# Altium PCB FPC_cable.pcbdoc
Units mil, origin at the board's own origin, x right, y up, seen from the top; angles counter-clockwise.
Board outline 8390 x 1932.5 mil, 2 copper layers (Top Layer, Bottom Layer); 1 components, 14 nets, 59 pads, 21 vias.
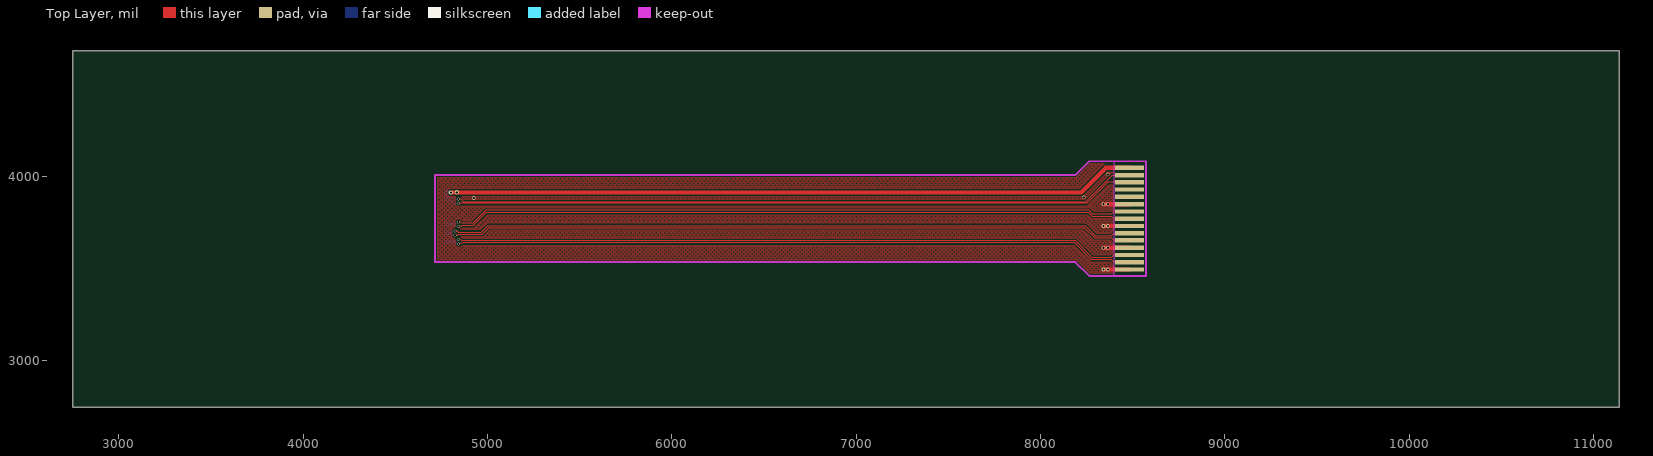
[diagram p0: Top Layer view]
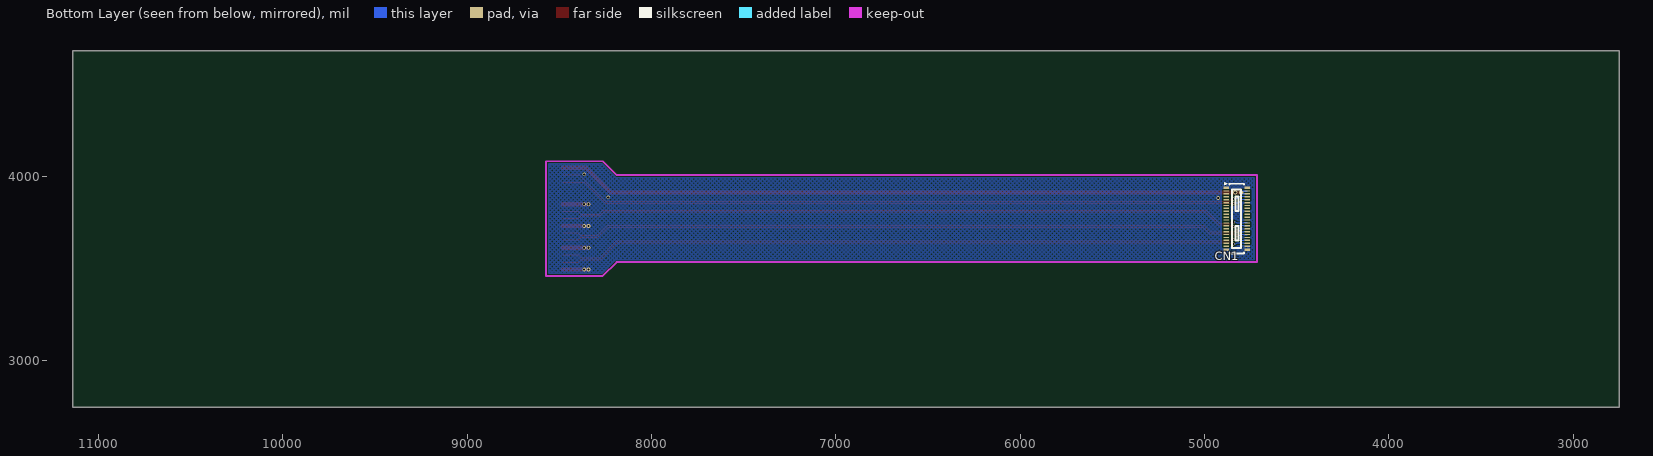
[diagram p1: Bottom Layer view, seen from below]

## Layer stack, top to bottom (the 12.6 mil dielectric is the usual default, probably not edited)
Top Layer: signal copper (thickness not stored)
Dielectric: dielectric 12.6, FR-4, Dk 4.8
Bottom Layer: signal copper (thickness not stored)

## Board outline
11140,2750 2750,2750 2750,4682.5 11140,4682.5

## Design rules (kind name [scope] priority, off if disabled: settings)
BoardOutlineClearance copperThickness1oz [All] p0: genericclearance=10 ignorepadtopadclearanceinfootprint=FALSE except(0: Arc-SplitContinuation Track-SplitContinuation SMDPad-SplitContinuation THPad-SplitContinuation Via-SplitContinuation Fill-SplitContinuation Poly-SplitContinuation Region-SplitContinuation Text-SplitContinuation; 6: SMDPad-CutoutEdge THPad-CutoutEdge Via-CutoutEdge Fill-CutoutEdge Region-CutoutEdge; 11.8: Track-OutlineEdge SMDPad-OutlineEdge THPad-OutlineEdge Via-OutlineEdge Fill-OutlineEdge Region-OutlineEdge Poly-OutlineEdge Text-OutlineEdge Track-CutoutEdge)
BoardOutlineClearance copperThickness2oz [All] p0: genericclearance=10 ignorepadtopadclearanceinfootprint=FALSE except(0: Arc-SplitContinuation Track-SplitContinuation SMDPad-SplitContinuation THPad-SplitContinuation Via-SplitContinuation Fill-SplitContinuation Poly-SplitContinuation Region-SplitContinuation Text-SplitContinuation; 6: SMDPad-CutoutEdge THPad-CutoutEdge Via-CutoutEdge Fill-CutoutEdge Region-CutoutEdge; 11.8: Track-OutlineEdge SMDPad-OutlineEdge THPad-OutlineEdge Via-OutlineEdge Fill-OutlineEdge Region-OutlineEdge Poly-OutlineEdge Text-OutlineEdge Track-CutoutEdge)
BoardOutlineClearance copperThicknessInner0.5oz [All] p0: genericclearance=10 ignorepadtopadclearanceinfootprint=FALSE except(0: Arc-SplitContinuation Track-SplitContinuation SMDPad-SplitContinuation THPad-SplitContinuation Via-SplitContinuation Fill-SplitContinuation Poly-SplitContinuation Region-SplitContinuation Text-SplitContinuation; 6: SMDPad-CutoutEdge THPad-CutoutEdge Via-CutoutEdge Fill-CutoutEdge Region-CutoutEdge; 11.8: Track-OutlineEdge SMDPad-OutlineEdge THPad-OutlineEdge Via-OutlineEdge Fill-OutlineEdge Region-OutlineEdge Poly-OutlineEdge Text-OutlineEdge Track-CutoutEdge)
Clearance copperThickness1oz [(InNet('GND') OR InNet('CSID0N') OR InNet('CSID0P') OR InNet('CSID1N') OR InNet('CSID1P') OR InNet('CSICN') OR InNet('CSICP') OR InNet('CSID2N') OR InNet('CSID2P') OR InNet('CSID3N') OR InNet('CSID3P') OR InNet('HOST_SCL') OR InNet('HOST_SDA') OR InNet('3V3'))] p1: gap=7 ignorepadtopadclearanceinfootprint=FALSE except(4: Track-Track; 6: Track-SMDPad SMDPad-SMDPad Track-THPad SMDPad-THPad THPad-THPad Track-Via SMDPad-Via THPad-Via Via-Via Track-Fill SMDPad-Fill THPad-Fill Via-Fill Fill-Fill SMDPad-Region THPad-Region Via-Region Fill-Region Region-Region Track-Poly SMDPad-Poly THPad-Poly Via-Poly Fill-Poly Poly-Poly Track-Text SMDPad-Text THPad-Text Via-Text Fill-Text Region-Text Poly-Text Text-Text; 6.9: Track-Hole SMDPad-Hole THPad-Hole Via-Hole Fill-Hole Region-Hole Poly-Hole Text-Hole Sheet-Hole; 11.8: Track-Region Region-Poly Track-Sheet SMDPad-Sheet THPad-Sheet Via-Sheet Fill-Sheet Region-Sheet Poly-Sheet Text-Sheet)
Clearance copperThickness2oz [All] p1: gap=7 ignorepadtopadclearanceinfootprint=FALSE except(6: Track-SMDPad SMDPad-SMDPad Track-THPad SMDPad-THPad THPad-THPad Track-Via SMDPad-Via THPad-Via Via-Via Track-Fill SMDPad-Fill THPad-Fill Via-Fill Fill-Fill SMDPad-Region THPad-Region Via-Region Fill-Region Region-Region Track-Poly SMDPad-Poly THPad-Poly Via-Poly Fill-Poly Poly-Poly Track-Text SMDPad-Text THPad-Text Via-Text Fill-Text Region-Text Poly-Text Text-Text; 6.9: Track-Hole SMDPad-Hole THPad-Hole Via-Hole Fill-Hole Region-Hole Poly-Hole Text-Hole Sheet-Hole; 8: Track-Track; 11.8: Track-Region Region-Poly Track-Sheet SMDPad-Sheet THPad-Sheet Via-Sheet Fill-Sheet Region-Sheet Poly-Sheet Text-Sheet)
Clearance copperThicknessInner0.5oz [All] p1: gap=7 ignorepadtopadclearanceinfootprint=FALSE except(3.5: Track-Track; 6: Track-SMDPad SMDPad-SMDPad Track-THPad SMDPad-THPad THPad-THPad Track-Via SMDPad-Via THPad-Via Via-Via Track-Fill SMDPad-Fill THPad-Fill Via-Fill Fill-Fill SMDPad-Region THPad-Region Via-Region Fill-Region Region-Region Track-Poly SMDPad-Poly THPad-Poly Via-Poly Fill-Poly Poly-Poly Track-Text SMDPad-Text THPad-Text Via-Text Fill-Text Region-Text Poly-Text Text-Text; 6.9: Track-Hole SMDPad-Hole THPad-Hole Via-Hole Fill-Hole Region-Hole Poly-Hole Text-Hole Sheet-Hole; 11.8: Track-Region Region-Poly Track-Sheet SMDPad-Sheet THPad-Sheet Via-Sheet Fill-Sheet Region-Sheet Poly-Sheet Text-Sheet)
DiffPairsRouting differentialPair [All] p1: maxuncoupledlength=10 minlimit=5.9843 maxlimit=5.9843 mostfreqgap=5.9843 toplayer_minwidth=5 toplayer_prefwidth=10 toplayer_maxwidth=100 bottomlayer_minwidth=5 bottomlayer_prefwidth=10 bottomlayer_maxwidth=100
PasteMaskExpansion pasteMaskExpansion [All] p1: expansion=0
PlaneConnect innerPlane [All] p1: planeconnectstyle=Relief reliefexpansion=20 reliefentries=4 reliefconductorwidth=10 reliefairgap=10
PolygonConnect copperRegion [All] p1: connectstyle=Direct reliefentries=4 reliefconductorwidth=10 polygonreliefangle="90 Angle" airgapwidth=10
RoutingVias viaSize [All] p1: viastyle="Through Hole" holewidth=12.0078 minholewidth=7.874 maxholewidth=248.0316 width=24.0158 minwidth=11.811 maxwidth=393.7008
SolderMaskExpansion solderMaskExpansion [All] p1: useseparateexpansions=TRUE expansion=2.0079 expansionbottom=2.0079
Width copperThickness1oz [All] p1: maxlimit=100 minlimit=4 preferedwidth=10
Width copperThickness2oz [All] p1: maxlimit=100 minlimit=8 preferedwidth=10
Width copperThickness0.5oz [All] p1: maxlimit=100 minlimit=4 preferedwidth=10

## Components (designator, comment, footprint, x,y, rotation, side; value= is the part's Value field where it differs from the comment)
CN1 "DF40C-40DP-0.4V(51)" CONN-SMD_DF40C-40DP-0.4V 4825,3772.5 r270 bottom

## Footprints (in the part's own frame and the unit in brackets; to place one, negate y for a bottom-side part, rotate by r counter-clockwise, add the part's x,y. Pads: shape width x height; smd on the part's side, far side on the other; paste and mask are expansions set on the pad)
CONN-SMD_DF40C-40DP-0.4V [mm]
  rect 0.19x0.75 smd: 1(-3.8,-1.455) 2(-3.8,1.455) 3(-3.4,-1.455) 4(-3.4,1.455) 5(-3,-1.455) 6(-3,1.455) 7(-2.6,-1.455) 8(-2.6,1.455) 9(-2.2,-1.455) 10(-2.2,1.455) 11(-1.8,-1.455) 12(-1.8,1.455) 13(-1.4,-1.455) 14(-1.4,1.455) 15(-1,-1.455) 16(-1,1.455) 17(-0.6,-1.455) 18(-0.6,1.455) 19(-0.2,-1.455) 20(-0.2,1.455) 21(0.2,-1.455) 22(0.2,1.455) 23(0.6,-1.455) 24(0.6,1.455) 25(1,-1.455) 26(1,1.455) 27(1.4,-1.455) 28(1.4,1.455) 29(1.8,-1.455) 30(1.8,1.455) 31(2.2,-1.455) 32(2.2,1.455) 33(2.6,-1.455) 34(2.6,1.455) 35(3,-1.455) 36(3,1.455) 37(3.4,-1.455) 38(3.4,1.455) 39(3.8,-1.455) 40(3.8,1.455)
  rect 0.35x0.75 smd: 41(4.275,-1.455) 42(4.275,1.455) 43(-4.275,1.455) 44(-4.275,-1.455)
  silkscreen extent -5,-1.7 4.83,1.02

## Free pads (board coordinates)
  rect 157.48x23.6 smd: 1(8482.72,3496.35) 2(8482.72,3536.28) 3(8482.72,3575.08) 4(8482.72,3614.46) 5(8482.72,3654.39) 6(8482.72,3693.19) 7(8482.72,3732.57) 8(8482.72,3772.5) 9(8482.72,3811.3) 10(8482.72,3850.67) 11(8482.72,3890.6) 12(8482.72,3930) 13(8482.72,3968.77) 14(8482.7,4007.5) 15(8482.72,4047.5)

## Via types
v1: diameter 19.7, hole 12, Top Layer to Bottom Layer, 11 vias
v2: diameter 15.7, hole 11.8, Top Layer to Bottom Layer, 8 vias
v3: diameter 24.02, hole 12.01, Top Layer to Bottom Layer, 2 vias

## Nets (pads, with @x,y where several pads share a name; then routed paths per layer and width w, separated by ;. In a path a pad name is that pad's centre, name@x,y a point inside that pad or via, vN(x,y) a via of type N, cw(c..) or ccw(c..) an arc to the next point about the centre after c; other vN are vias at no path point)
3V3: CN1.2 CN1.4 pad.15 | length 3810.3
  Top Layer w23.6: v3(4801.38,3914.25) v3@4833.11,3914.25 ; v3(4833.16,3914.3) 8221.8,3914.3 8355,4047.5 pad.15
  Bottom Layer w7.9: CN1.4 4793.48,3906.36 v3(4801.38,3914.25) 4793.52,3922.11 CN1.2
CSICN: CN1.26 pad.8 | length 3764.8
  Top Layer w5: v2(4842.6,3729.11) 4855.45,3729.11 4861.86,3735.52 4923.02,3735.52 4994,3806.5 8260.47,3806.5 8280.56,3786.41 8385.07,3786.41 8398.98,3772.5 pad.8
  Bottom Layer w5: CN1.26 4787.48,3733.13 4789.87,3735.52 4823.34,3735.52 4829.75,3729.11 v2(4842.6,3729.11)
CSICP: CN1.24 pad.9 | length 3764.8
  Top Layer w5: v2(4842.6,3752.91) 4855.45,3752.91 4861.86,3746.5 4918.47,3746.5 4989.47,3817.5 8265,3817.5 8285.11,3797.39 8385.07,3797.39 8398.98,3811.3 pad.9
  Bottom Layer w5: CN1.24 4787.48,3748.88 4789.85,3746.5 4823.34,3746.5 4829.75,3752.91 v2(4842.6,3752.91)
CSID0N: CN1.38 pad.2 | length 3764.7
  Top Layer w5: v2(4842.6,3634.62) 4855.45,3634.62 4861.86,3641.03 8185.94,3641.03 8276.78,3550.19 8385.07,3550.19 8398.98,3536.28 pad.2
  Bottom Layer w5: CN1.38 4787.48,3638.64 4789.87,3641.03 4823.34,3641.03 4829.75,3634.62 v2(4842.6,3634.62)
CSID0P: CN1.36 pad.3 | length 3764.7
  Top Layer w5: v2(4842.6,3658.42) 4855.45,3658.42 4861.86,3652.01 8190.49,3652.01 8281.33,3561.17 8385.07,3561.17 8398.98,3575.08 pad.3
  Bottom Layer w5: CN1.36 4787.48,3654.39 4789.85,3652.01 4823.34,3652.01 4829.75,3658.42 v2(4842.6,3658.42)
CSID1N: CN1.32 pad.5 | length 3764.5
  Top Layer w5: v2(4822.6,3681.87) 4835.45,3681.87 4841.86,3688.28 4971.31,3688.28 5006.55,3723.52 8238.45,3723.52 8293.67,3668.3 8385.07,3668.3 8398.98,3654.39 pad.5
  Bottom Layer w5: CN1.32 4787.48,3685.89 4789.86,3688.27 4803.35,3688.27 4809.75,3681.87 v2(4822.6,3681.87)
CSID1P: CN1.30 pad.6 | length 3764.5
  Top Layer w5: v2(4822.6,3705.67) 4835.45,3705.67 4841.86,3699.26 4966.76,3699.26 5002,3734.5 8243,3734.5 8298.22,3679.28 8385.07,3679.28 8398.98,3693.19 pad.6
  Bottom Layer w5: CN1.30 4787.48,3701.64 4789.86,3699.25 4803.33,3699.25 4809.75,3705.67 v2(4822.6,3705.67)
CSID2N: CN1.20
CSID2P: CN1.18
CSID3N: CN1.14
CSID3P: CN1.12
GND: CN1.10 CN1.16 CN1.22 CN1.28 CN1.34 CN1.40 CN1.41 CN1.42 CN1.43 CN1.44 pad.1 pad.4 pad.7 pad.10 | length 563
  Top Layer w23.6: v1(8341.96,3496.35) v1(8365.95,3496.35) pad.1 ; v1(8341.96,3614.46) v1(8365.95,3614.46) pad.4 ; v1(8341.96,3732.57) v1(8365.95,3732.57) pad.7 ; v1(8341.96,3850.67) v1(8365.95,3850.67) pad.10
  other v1: 4925,3884.5 8235,3887.5 8365,4012.5
HOST_SCL: CN1.8 pad.13 | length 3770.3
  Top Layer w5: v2(4842.6,3855.1) 8250.35,3855.1 8364.02,3968.77 pad.13
  Bottom Layer w5: CN1.8 4797.63,3874.87 4817.4,3855.1 v2(4842.6,3855.1)
HOST_SDA: CN1.6 pad.14 | length 3785.3
  Top Layer w5: v2(4842.6,3878.9) 4853.6,3878.9 4868.38,3864.12 8246.62,3864.12 8390,4007.5 pad.14
  Bottom Layer w5: CN1.6 4811.89,3890.61 4823.6,3878.9 v2(4842.6,3878.9)
pads on no net: CN1.1 CN1.3 CN1.5 CN1.7 CN1.9 CN1.11 CN1.13 CN1.15 CN1.17 CN1.19 CN1.21 CN1.23 CN1.25 CN1.27 CN1.29 CN1.31 CN1.33 CN1.35 CN1.37 CN1.39

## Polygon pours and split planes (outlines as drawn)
GND on Top Layer (hatched 45Degree grid 16 track 8, remove dead copper, pour order 0): 4465,4432.5 9150,4432.5 9150,3027.5 4465,3027.5
GND on Bottom Layer (hatched 45Degree grid 16 track 8, remove dead copper, pour order 4): 4442.5,4405 9127.5,4405 9127.5,3000 4442.5,3000
3V3 on Bottom Layer (solid, remove dead copper, pour order 2): 4752,3926.5 4848,3926.5 4848,3901.5 4752,3901.5

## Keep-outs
Top Layer:
  region: 8401.55,4083.52 8573.27,4083.52 8573.27,3461.48 8401.55,3461.48
Board Outline Layer:
  lines w10: 8190,4008.72 4715,4008.72 4715,3536.28 8190,3536.28 8264.8,3461.48 8573.27,3461.48 8573.27,4083.52 8264.8,4083.52 8190,4008.72 ; 8190,4008.72 8190,4008.72

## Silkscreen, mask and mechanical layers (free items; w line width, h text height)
Mech6:
  lines w10: 4715,3536.28 4935,3536.28 4935,4008.72 4715,4008.72 4715,3536.28 ; 8388.27,3461.48 8573.31,3461.48 8573.31,4083.52 8388.27,4083.52 8388.27,3461.48
  text "文档层框选区域 / 4.7mm*15.8mm / 金手指 / PI补强后总厚度0.24" at 8670,3487.5 h120
  text "文档层框选区域 / 5.588mm*12mm / 板对板连接器 / PI补强后总厚度0.5 / 如果只能一个厚度的话， / 就和金手指做一个厚度" at 3000,3202.5 h120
